// Mitsubishi GX Works2 project: 称重   PLC: FX3U/FX3UC

PROGRAM MAIN
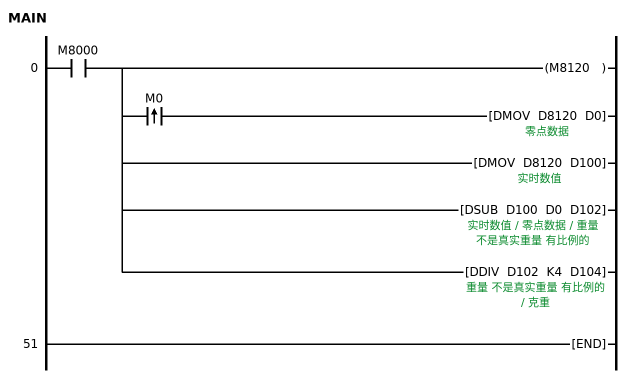
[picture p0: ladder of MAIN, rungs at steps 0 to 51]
0     LD      M8000
      OUT     M8120
      MPS
      ANDP    M0
      DMOV    D8120 D0  ; 零点数据
      MPP
      DMOV    D8120 D100  ; 实时数值
      DSUB    D100 D0 D102  ; 重量 不是真实重量 有比例的
      DDIV    D102 K4 D104  ; 克重
51    END
END_PROGRAM

// device comments not shown above
D2  ; 校准
